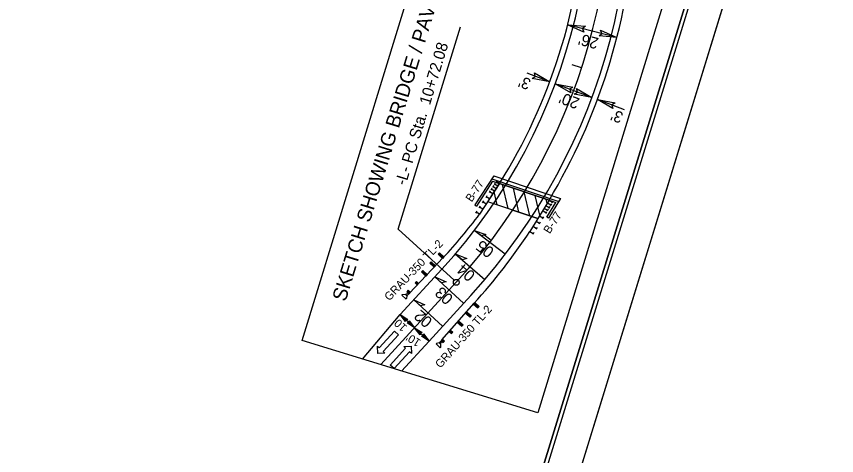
# Model space of a CAD drawing. Extents: x 1347957 to 1349499, y 1028289 to 1030503.
# Drawn here: x 1348996 to 1349499, y 1029396 to 1029665 of the extents above; entities that cross this region are included whole.
import ezdxf

# ---------------------------------------------------------------- set-up
doc = ezdxf.new("R2010")
doc.units = 0
for name, color, linetype in [('Default', 7, 'Continuous'), ('Prop Dimension', 7, 'Continuous'), ('Prop EOT', 7, 'Continuous'), ('Prop Guardrail', 7, 'Continuous'), ('Prop Guardrail Anchor Unit CELL', 7, 'Continuous'), ('Prop Horizontal Alignment', 7, 'Continuous'), ('Prop Horizontal Alignment Station Label', 7, 'Continuous'), ('Prop Horizontal Alignment Tick Small', 7, 'Continuous'), ('Prop Lane Arrow CELL', 7, 'Continuous'), ('Prop Roadway Bridge', 7, 'Continuous'), ('Prop Structure Anchor Unit CELL', 7, 'Continuous'), ('Prop Superelevation  Arrow CELL', 7, 'Continuous'), ('Prop Superelevation Label', 7, 'Continuous'), ('Prop Terminator CELL', 7, 'Continuous'), ('Sheet Clip Boundary CELL', 7, 'Continuous'), ('Sheet Cutting Line CELL', 7, 'Continuous'), ('Sheet Layout Plan Border', 7, 'Continuous'), ('Sheet Plan CELL', 7, 'Continuous'), ('Sheet Plan Layout CELL', 7, 'Continuous'), ('Sheet Plot Border Inside CELL', 7, 'Continuous'), ('Sheet Plot Border Outside CELL', 7, 'Continuous')]:
    doc.layers.add(name, color=color, linetype=linetype)

msp = doc.modelspace()

# ---------------------------------------------------------------- linework, layer by layer
at = {"layer": 'Default'}
for p, q in [((1349288.66, 1029567.51), (1349277.18, 1029549.76)), ((1349287.99, 1029564.26), (1349278.16, 1029549.07)), ((1349329.71, 1029553.72), (1349322.36, 1029541.63)), ((1349277.18, 1029549.76), (1349278.16, 1029549.07)), ((1349321.34, 1029542.25), (1349326.79, 1029551.22)), ((1349322.36, 1029541.63), (1349321.34, 1029542.25))]:
    msp.add_line(p, q, dxfattribs=at)
for points in [[(1349288.66, 1029567.51), (1349329.71, 1029553.72)], [(1349287.48, 1029565.69), (1349328.6, 1029551.88)], [(1349287.48, 1029565.69), (1349328.6, 1029551.88)], [(1349287.99, 1029564.26), (1349291.5, 1029563.08)], [(1349322.62, 1029552.62), (1349326.79, 1029551.22)]]:
    msp.add_lwpolyline(points, dxfattribs=at)
at = {"layer": 'Prop Dimension'}
for p, q in [((1349364.27, 1029652.51), (1349334.04, 1029660.24)), ((1349323.07, 1029625.24), (1349309.12, 1029630.44)), ((1349348.93, 1029615.6), (1349326.44, 1029623.98)), ((1349368.99, 1029608.11), (1349352.3, 1029614.34)), ((1349248.98, 1029466.29), (1349231.29, 1029482.51))]:
    msp.add_line(p, q, dxfattribs=at)
msp.add_lwpolyline([(1349171.26, 1029466.55), (1349289.82, 1029852.82), (1349434.23, 1029808.5), (1349315.67, 1029422.23)], close=True, dxfattribs=at)
at = {"layer": 'Prop EOT'}
for p, q in [((1349231.29, 1029482.51), (1349256.86, 1029510.39)), ((1349248.98, 1029466.28), (1349274.55, 1029494.17)), ((1349208.1, 1029455.24), (1349231.29, 1029482.51)), ((1349256.48, 1029474.47), (1349256.65, 1029474.65)), ((1349232.07, 1029447.89), (1349248.98, 1029466.28))]:
    msp.add_line(p, q, dxfattribs=at)
for radius, end in [(348, 15.5258), (372, 13.1925)]:
    msp.add_arc((1349000.38, 1029745.6), radius, 317.4777, end, dxfattribs=at)
at = {"layer": 'Prop Guardrail'}
for centre, radius, start, end in [((1349005.23, 1029751.39), 344.23, 317.1803, 322.9499), ((1348996.59, 1029742.87), 377.7, 317.8551, 326.3203)]:
    msp.add_arc(centre, radius, start, end, dxfattribs=at)
at = {"layer": 'Prop Guardrail Anchor Unit CELL'}
for p, q in [((1349237.01, 1029495.71), (1349257.72, 1029517.41)), ((1349255.5, 1029520.36), (1349254.67, 1029519.49)), ((1349257.31, 1029516.98), (1349254.67, 1029519.49)), ((1349254.67, 1029519.49), (1349256.82, 1029519.11)), ((1349258.14, 1029517.85), (1349255.5, 1029520.36)), ((1349255.99, 1029518.24), (1349255.5, 1029520.36)), ((1349256.82, 1029519.11), (1349255.99, 1029518.24)), ((1349258.14, 1029517.85), (1349255.99, 1029518.24)), ((1349256.82, 1029519.11), (1349257.31, 1029516.98)), ((1349258.14, 1029517.85), (1349257.31, 1029516.98)), ((1349250.33, 1029514.94), (1349249.5, 1029514.07)), ((1349252.13, 1029511.55), (1349249.5, 1029514.07)), ((1349249.5, 1029514.07), (1349251.64, 1029513.68)), ((1349252.96, 1029512.42), (1349250.33, 1029514.94)), ((1349250.81, 1029512.81), (1349250.33, 1029514.94)), ((1349251.64, 1029513.68), (1349250.81, 1029512.81)), ((1349252.96, 1029512.42), (1349250.81, 1029512.81)), ((1349251.64, 1029513.68), (1349252.13, 1029511.55)), ((1349252.96, 1029512.42), (1349252.13, 1029511.55)), ((1349245.15, 1029509.51), (1349244.32, 1029508.64)), ((1349246.96, 1029506.13), (1349244.32, 1029508.64)), ((1349244.32, 1029508.64), (1349246.47, 1029508.25)), ((1349247.78, 1029507), (1349245.15, 1029509.51)), ((1349245.64, 1029507.38), (1349245.15, 1029509.51)), ((1349246.47, 1029508.25), (1349245.64, 1029507.38)), ((1349247.78, 1029507), (1349245.64, 1029507.38)), ((1349246.47, 1029508.25), (1349246.96, 1029506.13)), ((1349247.78, 1029507), (1349246.96, 1029506.13)), ((1349241.29, 1029502.83), (1349240.46, 1029501.96)), ((1349241.78, 1029500.7), (1349240.46, 1029501.96)), ((1349242.61, 1029501.57), (1349240.46, 1029501.96)), ((1349242.61, 1029501.57), (1349241.29, 1029502.83)), ((1349241.29, 1029502.83), (1349241.78, 1029500.7)), ((1349236.11, 1029497.4), (1349235.28, 1029496.53)), ((1349237.43, 1029496.14), (1349236.11, 1029497.4)), ((1349236.11, 1029497.4), (1349236.6, 1029495.27)), ((1349242.61, 1029501.57), (1349241.78, 1029500.7)), ((1349232.59, 1029494.71), (1349232.34, 1029494.45)), ((1349234.89, 1029492.01), (1349232.34, 1029494.45)), ((1349232.59, 1029494.71), (1349234.31, 1029495.02)), ((1349234.31, 1029495.02), (1349235.37, 1029494.01)), ((1349234.75, 1029494.61), (1349235.97, 1029495.88)), ((1349235.14, 1029492.27), (1349234.89, 1029492.01)), ((1349235.37, 1029494.01), (1349235.14, 1029492.27)), ((1349236.6, 1029495.27), (1349235.28, 1029496.53)), ((1349237.43, 1029496.14), (1349235.28, 1029496.53)), ((1349236.59, 1029495.28), (1349235.37, 1029494.01)), ((1349237.43, 1029496.14), (1349236.6, 1029495.27)), ((1349256.78, 1029466.94), (1349276.64, 1029489.43)), ((1349277.03, 1029489.88), (1349276.24, 1029488.98)), ((1349276.24, 1029488.98), (1349278.97, 1029486.57)), ((1349278.4, 1029488.68), (1349276.24, 1029488.98)), ((1349277.03, 1029489.88), (1349279.76, 1029487.47)), ((1349277.03, 1029489.88), (1349277.6, 1029487.78)), ((1349278.4, 1029488.68), (1349277.6, 1029487.78)), ((1349277.6, 1029487.78), (1349279.76, 1029487.47)), ((1349278.97, 1029486.57), (1349278.4, 1029488.68)), ((1349279.76, 1029487.47), (1349278.97, 1029486.57)), ((1349272.07, 1029484.26), (1349271.28, 1029483.36)), ((1349271.28, 1029483.36), (1349274.01, 1029480.95)), ((1349273.44, 1029483.05), (1349271.28, 1029483.36)), ((1349272.07, 1029484.26), (1349274.8, 1029481.85)), ((1349272.07, 1029484.26), (1349272.64, 1029482.15)), ((1349273.44, 1029483.05), (1349272.64, 1029482.15)), ((1349272.64, 1029482.15), (1349274.8, 1029481.85)), ((1349274.01, 1029480.95), (1349273.44, 1029483.05)), ((1349274.8, 1029481.85), (1349274.01, 1029480.95)), ((1349267.11, 1029478.64), (1349266.31, 1029477.74)), ((1349266.31, 1029477.74), (1349269.04, 1029475.33)), ((1349268.47, 1029477.43), (1349266.31, 1029477.74)), ((1349267.11, 1029478.64), (1349269.84, 1029476.23)), ((1349267.11, 1029478.64), (1349267.68, 1029476.53)), ((1349268.47, 1029477.43), (1349267.68, 1029476.53)), ((1349269.04, 1029475.33), (1349268.47, 1029477.43)), ((1349262.14, 1029473.02), (1349261.35, 1029472.12)), ((1349261.35, 1029472.12), (1349262.71, 1029470.91)), ((1349263.51, 1029471.81), (1349261.35, 1029472.12)), ((1349262.14, 1029473.02), (1349263.51, 1029471.81)), ((1349262.14, 1029473.02), (1349262.71, 1029470.91)), ((1349263.51, 1029471.81), (1349262.71, 1029470.91)), ((1349267.68, 1029476.53), (1349269.84, 1029476.23)), ((1349269.84, 1029476.23), (1349269.04, 1029475.33)), ((1349257.18, 1029467.39), (1349256.38, 1029466.49)), ((1349256.38, 1029466.49), (1349257.75, 1029465.29)), ((1349258.54, 1029466.19), (1349256.38, 1029466.49)), ((1349257.18, 1029467.39), (1349258.54, 1029466.19)), ((1349257.18, 1029467.39), (1349257.75, 1029465.29)), ((1349253.52, 1029464.78), (1349253.28, 1029464.51)), ((1349253.28, 1029464.51), (1349255.92, 1029462.18)), ((1349255.23, 1029465.16), (1349253.52, 1029464.78)), ((1349256.39, 1029466.49), (1349255.23, 1029465.16)), ((1349256.33, 1029464.19), (1349255.23, 1029465.16)), ((1349255.88, 1029464.59), (1349257.04, 1029465.91)), ((1349256.17, 1029462.45), (1349255.92, 1029462.18)), ((1349256.17, 1029462.45), (1349256.33, 1029464.19)), ((1349258.54, 1029466.19), (1349257.75, 1029465.29))]:
    msp.add_line(p, q, dxfattribs=at)
at = {"layer": 'Prop Horizontal Alignment'}
msp.add_line((1349219.39, 1029451.78), (1349265.71, 1029502.28), dxfattribs=at)
msp.add_arc((1349000.38, 1029745.6), 360, 317.4777, 14.313, dxfattribs=at)
at = {"layer": 'Prop Horizontal Alignment Station Label'}
for p, q in [((1349230.11, 1029534.93), (1349268.3, 1029658.93)), ((1349264.38, 1029503.5), (1349230.11, 1029534.93))]:
    msp.add_line(p, q, dxfattribs=at)
msp.add_circle((1349265.71, 1029502.28), 1.8, dxfattribs=at)
at = {"layer": 'Prop Horizontal Alignment Tick Small'}
for p, q in [((1349342.59, 1029633.81), (1349336.88, 1029635.67)), ((1349287.17, 1029527.99), (1349282.39, 1029531.62))]:
    msp.add_line(p, q, dxfattribs=at)
at = {"layer": 'Prop Lane Arrow CELL'}
for p, q in [((1349218.42, 1029462.02), (1349227.88, 1029472.34)), ((1349227.88, 1029472.34), (1349230.31, 1029470.11)), ((1349230.31, 1029470.11), (1349220.85, 1029459.79)), ((1349217.54, 1029458.55), (1349217.31, 1029463.04)), ((1349217.31, 1029463.04), (1349218.42, 1029462.02)), ((1349225.16, 1029451.56), (1349234.62, 1029461.88)), ((1349233.52, 1029462.9), (1349237.93, 1029463.12)), ((1349234.62, 1029461.88), (1349233.52, 1029462.9)), ((1349237.93, 1029463.12), (1349238.16, 1029458.64)), ((1349221.95, 1029458.78), (1349217.54, 1029458.55)), ((1349220.85, 1029459.79), (1349221.95, 1029458.78)), ((1349237.05, 1029459.65), (1349227.59, 1029449.33)), ((1349238.16, 1029458.64), (1349237.05, 1029459.65)), ((1349227.59, 1029449.33), (1349225.16, 1029451.56))]:
    msp.add_line(p, q, dxfattribs=at)
at = {"layer": 'Prop Roadway Bridge'}
for p, q in [((1349322.62, 1029552.62), (1349292.28, 1029562.81)), ((1349297.48, 1029547.55), (1349294.07, 1029562.21)), ((1349290.8, 1029549.8), (1349288.96, 1029557.73)), ((1349304.16, 1029545.31), (1349300.75, 1029559.97)), ((1349310.84, 1029543.06), (1349307.44, 1029557.72)), ((1349316.91, 1029543.46), (1349314.12, 1029555.48)), ((1349321.4, 1029550.66), (1349320.8, 1029553.23)), ((1349300.37, 1029546.58), (1349285.04, 1029551.73)), ((1349300.37, 1029546.58), (1349315.66, 1029541.45))]:
    msp.add_line(p, q, dxfattribs=at)
msp.add_lwpolyline([(1349292.28, 1029562.81), (1349322.62, 1029552.62), (1349315.66, 1029541.45), (1349285.04, 1029551.73)], close=True, dxfattribs=at)
for radius, start, end in [(344.4, 327.9454, 357.1202), (375.6, 329.0842, 355.7877)]:
    msp.add_arc((1349000.38, 1029745.6), radius, start, end, dxfattribs=at)
at = {"layer": 'Prop Structure Anchor Unit CELL'}
for p, q in [((1349292.28, 1029562.81), (1349279.97, 1029543.98)), ((1349289.62, 1029563.13), (1349288.87, 1029561.98)), ((1349291.25, 1029561.25), (1349289.24, 1029562.56)), ((1349290.64, 1029564.7), (1349289.89, 1029563.55)), ((1349292.28, 1029562.81), (1349290.27, 1029564.13)), ((1349286.54, 1029558.43), (1349285.79, 1029557.27)), ((1349288.17, 1029556.54), (1349286.16, 1029557.85)), ((1349287.57, 1029559.99), (1349286.81, 1029558.84)), ((1349289.2, 1029558.11), (1349287.19, 1029559.42)), ((1349288.59, 1029561.56), (1349287.84, 1029560.41)), ((1349290.23, 1029559.68), (1349288.22, 1029560.99)), ((1349282.44, 1029552.15), (1349281.69, 1029551)), ((1349284.49, 1029555.29), (1349283.74, 1029554.14)), ((1349286.12, 1029553.4), (1349284.11, 1029554.71)), ((1349322.62, 1029552.62), (1349310.89, 1029533.42)), ((1349322.62, 1029552.62), (1349324.67, 1029551.37)), ((1349280.39, 1029549.01), (1349279.63, 1029547.86)), ((1349282.02, 1029547.12), (1349280.01, 1029548.43)), ((1349284.07, 1029550.26), (1349282.06, 1029551.57)), ((1349319.69, 1029547.82), (1349321.74, 1029546.57)), ((1349320.67, 1029549.42), (1349322.71, 1029548.17)), ((1349322.09, 1029547.16), (1349321.38, 1029545.98)), ((1349321.64, 1029551.02), (1349323.69, 1029549.77)), ((1349323.07, 1029548.76), (1349322.36, 1029547.58)), ((1349324.05, 1029550.36), (1349323.33, 1029549.18)), ((1349325.03, 1029551.96), (1349324.31, 1029550.78)), ((1349278.33, 1029545.87), (1349277.58, 1029544.72)), ((1349279.97, 1029543.98), (1349277.96, 1029545.29)), ((1349316.76, 1029543.02), (1349318.81, 1029541.77)), ((1349319.16, 1029542.36), (1349318.45, 1029541.18)), ((1349318.71, 1029546.22), (1349320.76, 1029544.97)), ((1349321.12, 1029545.56), (1349320.4, 1029544.38)), ((1349314.8, 1029539.82), (1349316.85, 1029538.57)), ((1349317.21, 1029539.16), (1349316.49, 1029537.98)), ((1349310.89, 1029533.42), (1349312.94, 1029532.17)), ((1349313.3, 1029532.75), (1349312.58, 1029531.58)), ((1349312.85, 1029536.62), (1349314.9, 1029535.37)), ((1349315.25, 1029535.96), (1349314.54, 1029534.78))]:
    msp.add_line(p, q, dxfattribs=at)
at = {"layer": 'Prop Superelevation  Arrow CELL'}
for p, q in [((1349295.79, 1029519.51), (1349276.74, 1029534.09)), ((1349265.07, 1029519.66), (1349283.32, 1029504.08)), ((1349270.23, 1029489.46), (1349252.54, 1029505.68)), ((1349239.57, 1029491.53), (1349257.26, 1029475.31))]:
    msp.add_line(p, q, dxfattribs=at)
for points in [[(1349276.74, 1029534.09), (1349283.91, 1029531.62), (1349281.14, 1029530.72)], [(1349265.07, 1029519.66), (1349272.1, 1029516.81), (1349269.29, 1029516.06)], [(1349252.54, 1029505.68), (1349259.47, 1029502.58), (1349256.63, 1029501.93)], [(1349239.57, 1029491.53), (1349246.5, 1029488.43), (1349243.66, 1029487.78)]]:
    msp.add_lwpolyline(points, close=True, dxfattribs=at)
at = {"layer": 'Prop Terminator CELL'}
for points in [[(1349344.04, 1029655.77), (1349334.04, 1029660.24), (1349345.04, 1029659.41), (1349343.22, 1029657.89)], [(1349354.26, 1029656.99), (1349364.27, 1029652.51), (1349353.27, 1029653.34), (1349355.08, 1029654.86)], [(1349313.6, 1029630.76), (1349323.07, 1029625.24), (1349312.22, 1029627.24), (1349314.19, 1029628.55)], [(1349335.91, 1029618.47), (1349326.44, 1029623.98), (1349337.29, 1029621.99), (1349335.32, 1029620.67)], [(1349339.46, 1029621.11), (1349348.93, 1029615.6), (1349338.08, 1029617.59), (1349340.05, 1029618.91)], [(1349361.77, 1029608.82), (1349352.3, 1029614.34), (1349363.15, 1029612.34), (1349361.18, 1029611.02)], [(1349234.64, 1029478.17), (1349231.29, 1029482.51), (1349235.94, 1029479.54), (1349234.79, 1029479.3)], [(1349236.79, 1029478.73), (1349240.14, 1029474.4), (1349235.49, 1029477.36), (1349236.64, 1029477.6)], [(1349243.49, 1029470.07), (1349240.14, 1029474.4), (1349244.79, 1029471.44), (1349243.64, 1029471.2)], [(1349245.62, 1029470.62), (1349248.98, 1029466.29), (1349244.33, 1029469.24), (1349245.48, 1029469.49)]]:
    msp.add_lwpolyline(points, close=True, dxfattribs=at)
at = {"layer": 'Sheet Clip Boundary CELL'}
msp.add_lwpolyline([(1349045.75, 1028502.32), (1349457.8, 1029840.32), (1348656.43, 1030087.11), (1348600.72, 1029906.23), (1348398.6, 1029968.48), (1348042.26, 1028811.35)], close=True, dxfattribs=at)
at = {"layer": 'Sheet Cutting Line CELL'}
msp.add_line((1349003.55, 1028288.8), (1349499.03, 1029897.73), dxfattribs=at)
at = {"layer": 'Sheet Layout Plan Border'}
msp.add_lwpolyline([(1349045.75, 1028502.32), (1349457.8, 1029840.32), (1348656.43, 1030087.11), (1348600.72, 1029906.23), (1348398.6, 1029968.48), (1348042.26, 1028811.35)], close=True, dxfattribs=at)
at = {"layer": 'Sheet Plan CELL'}
for points in [[(1348469.03, 1030197.17), (1348027.54, 1028763.57), (1349031.04, 1028454.54), (1349472.52, 1029888.11)], [(1349031.04, 1028454.54), (1348027.56, 1028763.54), (1348410.13, 1030005.96), (1348553.55, 1029961.8), (1348612.44, 1030152.98), (1349472.52, 1029888.11)]]:
    msp.add_lwpolyline(points, close=True, dxfattribs=at)
at = {"layer": 'Sheet Plan Layout CELL'}
msp.add_lwpolyline([(1348027.56, 1028763.54), (1349031.04, 1028454.54), (1349472.51, 1029888.1), (1348671.14, 1030134.89), (1348600.72, 1029906.23), (1348398.6, 1029968.48)], close=True, dxfattribs=at)
at = {"layer": 'Sheet Plot Border Inside CELL'}
msp.add_lwpolyline([(1348988.26, 1028307.11), (1349478.58, 1029899.31), (1348470.32, 1030209.82), (1347979.99, 1028617.61)], close=True, dxfattribs=at)
at = {"layer": 'Sheet Plot Border Outside CELL'}
msp.add_lwpolyline([(1349003.55, 1028288.8), (1349499.03, 1029897.73), (1348452.53, 1030220.01), (1347957.05, 1028611.07)], close=True, dxfattribs=at)

# ---------------------------------------------------------------- texts
at = {"layer": 'Prop Dimension'}
for s, height, rotation, p in [('SKETCH SHOWING BRIDGE / PAVEMENT RELATIONSHIP', 8.75, 72.9373, (1349197.77, 1029490.02)), ("26'", 7, 165.6508, (1349353.52, 1029651.92)), ("3'", 7, 159.5453, (1349312.09, 1029626.57)), ("20'", 7, 159.5453, (1349341.92, 1029614.82)), ("3'", 7, 159.5453, (1349368.76, 1029606.08)), ('B-77', 5, 56.8276, (1349275.19, 1029551.13)), ('B-77', 5, 56.8276, (1349322.97, 1029531.67)), ('GRAU-350 TL-2', 5, 46.3428, (1349224.62, 1029490.55)), ('GRAU-350 TL-2', 5, 48.5593, (1349256.01, 1029449.28)), ("10'", 5, 137.4777, (1349235.88, 1029475.16)), ("10'", 5, 147.557, (1349244.42, 1029466.58))]:
    msp.add_text(s, height=height, rotation=rotation, dxfattribs=at).set_placement(p)
at = {"layer": 'Prop Horizontal Alignment Station Label'}
msp.add_text('-L- PC Sta.  10+72.08', height=7, rotation=73.2015, dxfattribs=at).set_placement((1349234.65, 1029561.27))
at = {"layer": 'Prop Superelevation Label'}
for s, rotation, p in [('05', 142.5718, (1349289.48, 1029522.27)), ('04', 139.516, (1349277.9, 1029507.48)), ('03', 137.4777, (1349264.34, 1029493.07)), ('02', 139.3898, (1349251.58, 1029479.15))]:
    msp.add_text(s, height=7, rotation=rotation, dxfattribs=at).set_placement(p)

doc.saveas('drawing.dxf')
